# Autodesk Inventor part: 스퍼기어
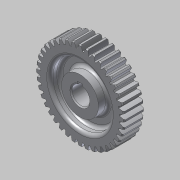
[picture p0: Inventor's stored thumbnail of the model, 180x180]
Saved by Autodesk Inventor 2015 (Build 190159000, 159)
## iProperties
Created: 2018-11
Part Number: 스퍼기어
Material: 알루미늄 6061
Document SubType Name: Modeling
Designer: mduedu
Categories: <?xml version="1.0" encoding="UTF-16"?> <MemberInstance><Categories><FamilyTemplate><FamilyTemplateParameter ValueType="xs:double" Id="1" ObjectReferenceKey="da
Density: 1 g/cm^3
Appearance: 알루미늄 - 평지
CustomPartVersion: 1
Author: mduedu
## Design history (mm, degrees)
sketch "Sketch1"
  geometry: C1 r 42 at (0, 0)
  constraints: 1 centre point
  dimensions: "d0" = 83.99905 diameter of C1 (= da_da)
extrude "Extrusion1" new body sketch "Sketch1" distance "d1" = 19 (= da_b); taper "d2" = 0 deg
workplane "Work Plane2"
sketch "Sketch2"
  geometry: C1 r 42 at (0, 0) reference; C2 r 40.05 at (0, 0)
  constraints: 1 centre point, 1 coincident
  dimensions: "d3" = 80.10038 diameter of C2 (= da_dw)
feature "피치 지름" sketch "Sketch2" dims "d4" = 10, "d5" = 0
workplane "Work Plane8"
workplane "Work Plane9"
feature "스퍼 기어" dims "da_b" = 19, "da_d" = 80, "da_aw" = 80.10038, "da_da" = 83.99905, "da_df" = 75, "da_dw" = 80.10038, angle "da_beta" = 0 deg, "da_lefttooth" = 0, "da_righttooth" = 0
sketch "스케치3"
  geometry: L1 (-42, 19)-(42, 19) reference; L2 (42, 19)-(42, 0) reference; L3 (42, 0)-(-42, 0) reference; L4 (-42, 0)-(-42, 19) reference; L5 (0, 0)-(0, 19); L6 (42, 0)-(41, 0); L7 (42, 1)-(42, 0); L8 (42, 19)-(41, 19); L9 (42, 18)-(42, 19); L10 (41, 19)-(42, 18); L11 (41, 0)-(42, 1)
  constraints: 14 end point, 2 horizontal, 2 vertical, 1 midpoint
  dimensions: "d49" = 1 distance from line of L8.end L2; "d50" = 1 horizontal distance of L8.end L9.start; "d51" = 1 horizontal distance of L6.end L7.start; "d52" = 1 horizontal distance of L6.end L7.start
revolve "회전1" sketch "스케치3" stored, may be unused: angle "d53" = 90 deg
sketch "스케치4"
  geometry: L1 (-2.5, 8.124)-(2.5, 8.124); L2 (2.5, 8.124)-(2.5, 10.8); L3 (2.5, 10.8)-(-2.5, 10.8); L4 (-2.5, 10.8)-(-2.5, 8.124); A1 r 8.5 centre (0, 0) between (-2.5, 8.124) and (2.5, 8.124); 1 further point
  constraints: 8 end point, 2 parallel, 2 point on circle, 1 centre point, 1 coincident, 1 horizontal, 1 perpendicular
  dimensions: "d54" = 17 diameter of A1; "d56" = 19.3 dimension on A1 L3; "d57" = 5 distance of L2.end L3.end
extrude "돌출2" cut sketch "스케치4" stored distance "d58" = 10; taper "d59" = 0 deg
chamfer "모따기1" distance "d60" = 1; stored, may be unused: second distance "d61" = 2, angle "d62" = 45 deg
sketch "스케치5"
  geometry: C1 r 17.5 at (0, 0); C2 r 28.5 at (0, 0); 1 further point
  constraints: 2 centre point, 2 coincident
  dimensions: "d63" = 35 diameter of C1; "d64" = 57 diameter of C2
extrude "돌출3" cut sketch "스케치5" distance "d65" = 9.5; taper "d66" = 0 deg
fillet "모깎기1" dims "d67" = 3
body "Solid1"
body "Srf1"
node "절단 모서리 투영1"
other parameters: "d16" = 80.10038 (= da_aw), "d17" = 0, "d34" = 4.5 deg (computed from da_z), "d39" = 0, "d41" = 0, "d43" = 80.10038 (= da_aw), "d46" = 80.10038 (= da_aw), "d47" = 0, "d48" = 0
